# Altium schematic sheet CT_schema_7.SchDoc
size 423 x 414 mm
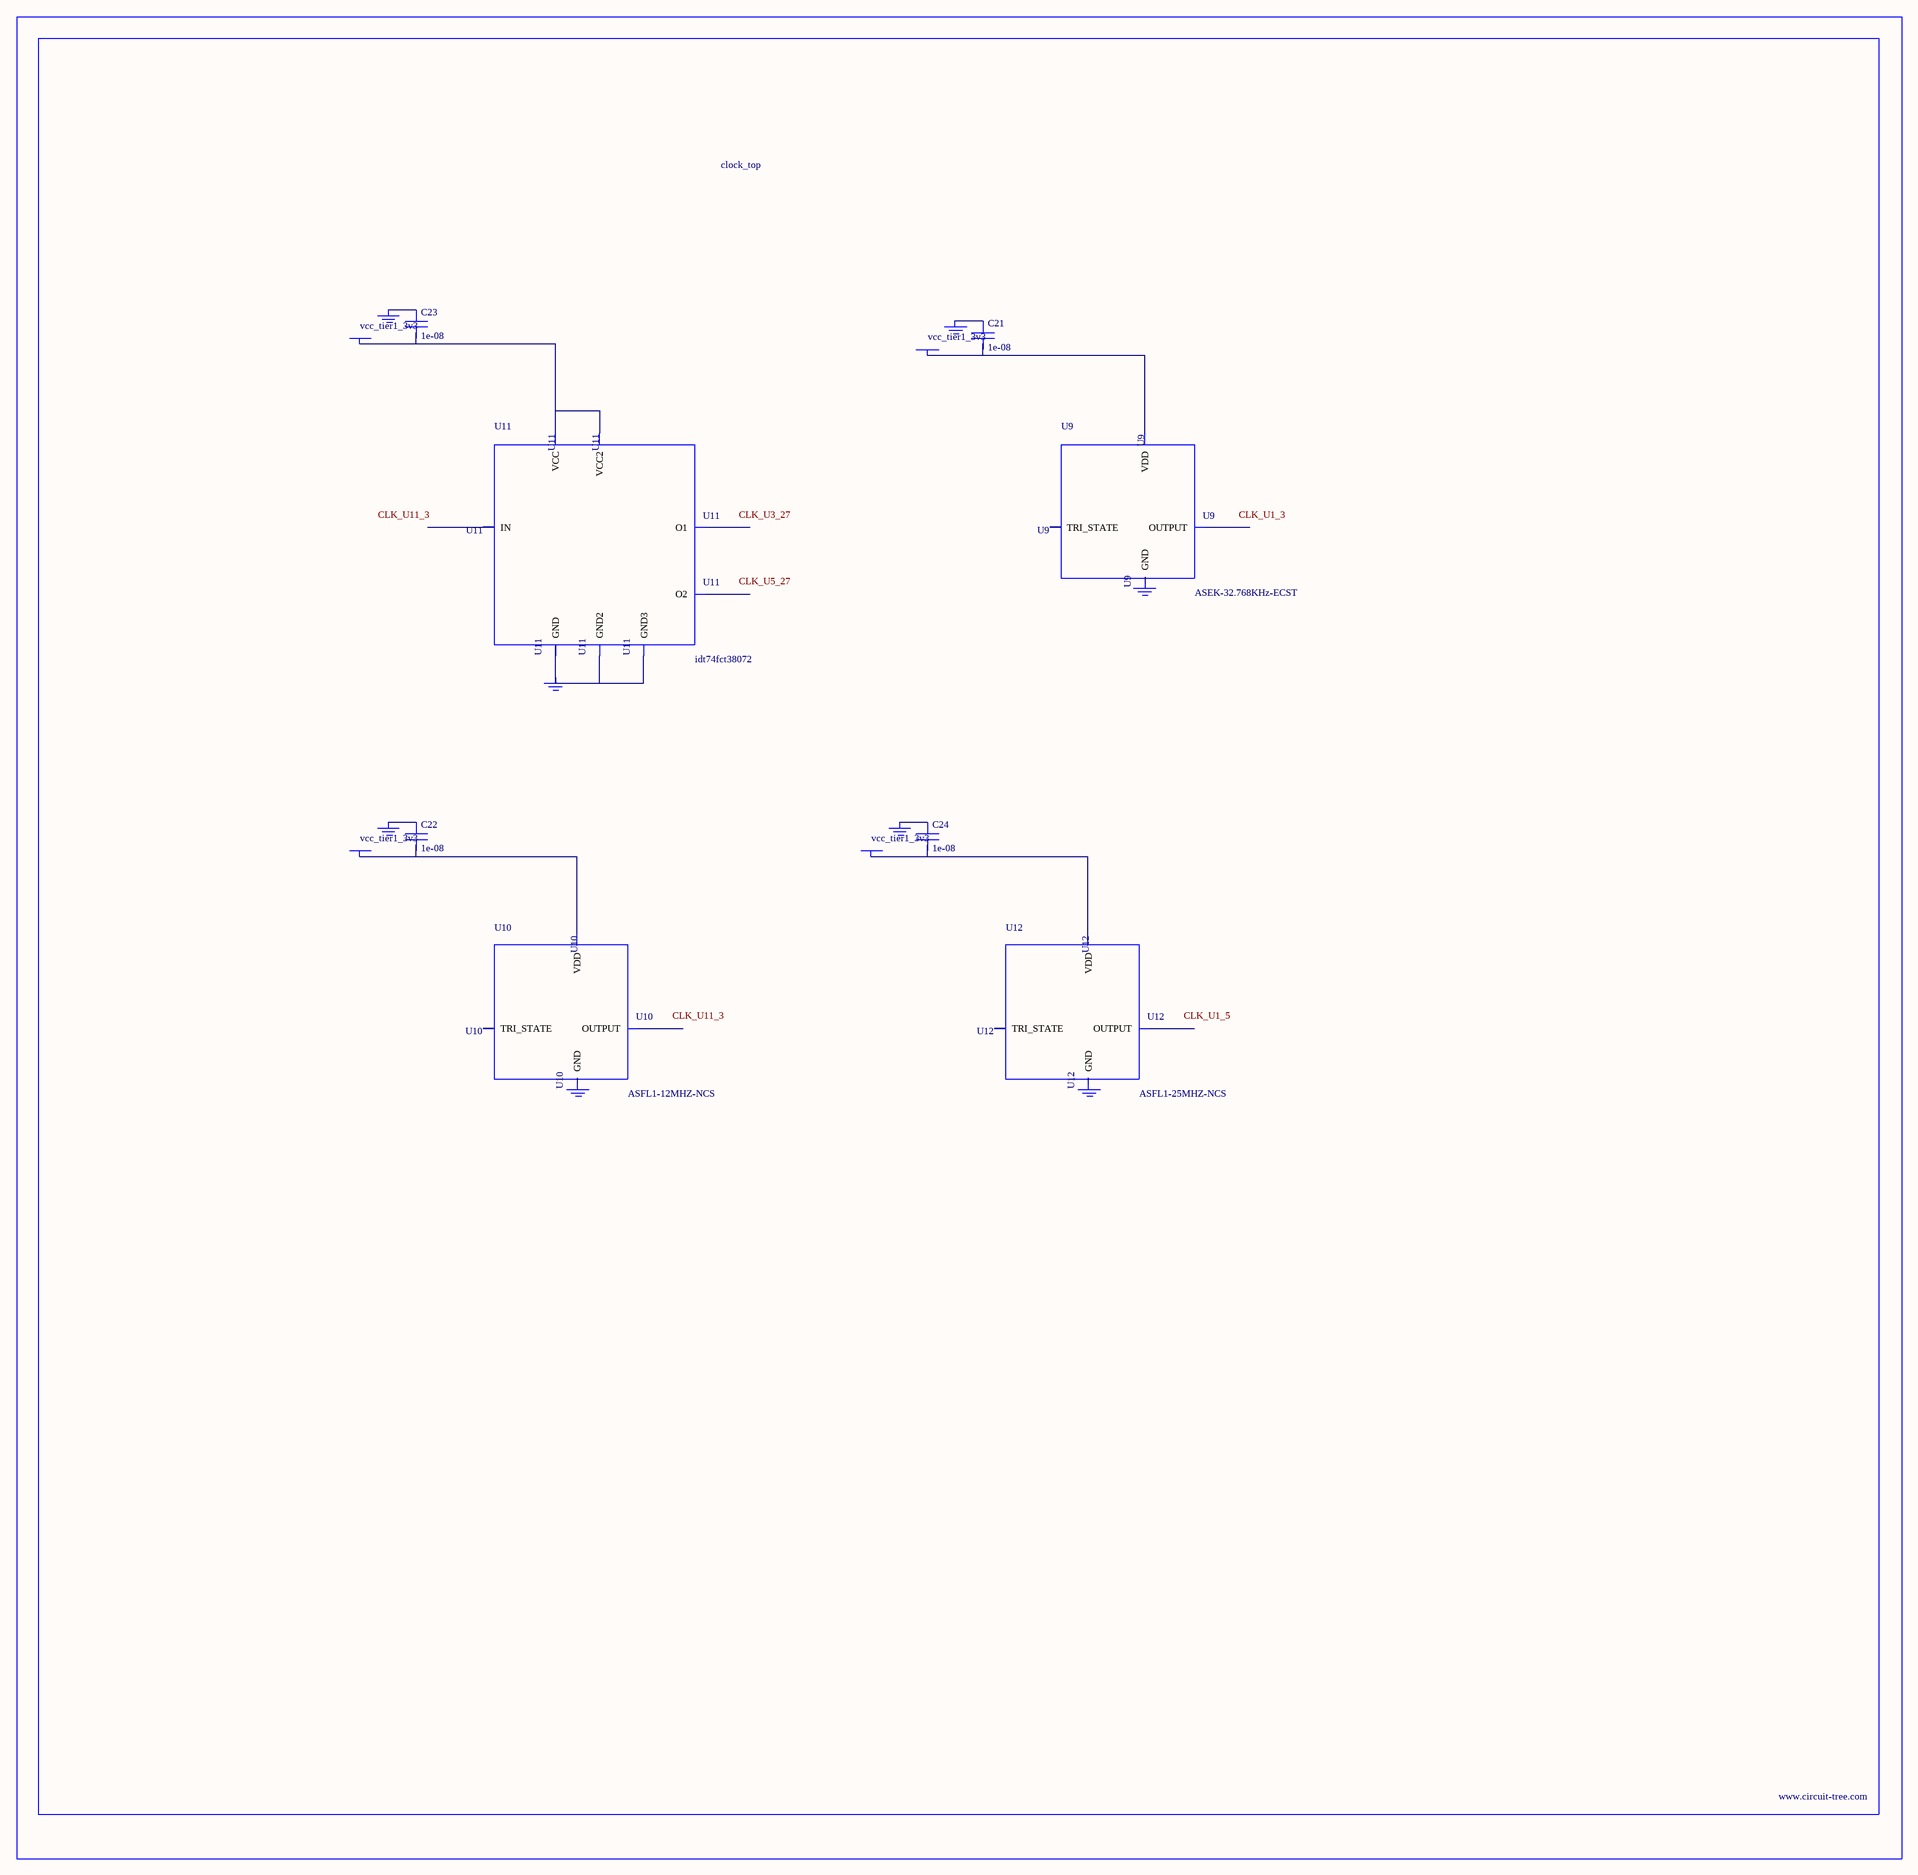
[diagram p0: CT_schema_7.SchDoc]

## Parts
BORDER6  (no value)
C21  1e-08  [C0402]
C22  1e-08  [C0402]
C23  1e-08  [C0402]
C24  1e-08  [C0402]
GND_INSTANCE_6_0  (no value)
GND_INSTANCE_6_1  (no value)
GND_INSTANCE_6_2  (no value)
GND_INSTANCE_6_3  (no value)
GND_INSTANCE_6_4  (no value)
GND_INSTANCE_6_5  (no value)
GND_INSTANCE_6_6  (no value)
GND_INSTANCE_6_7  (no value)
POWER_INSTANCE_6_0  vcc_tier1_3v3
POWER_INSTANCE_6_1  vcc_tier1_3v3
POWER_INSTANCE_6_2  vcc_tier1_3v3
POWER_INSTANCE_6_3  vcc_tier1_3v3
U9  ASEK-32.768KHz-ECST  [ASEK]
U10  ASFL1-12MHZ-NCS  [ASFL1]
U11  idt74fct38072  [IDT74FCT38072]
U12  ASFL1-25MHZ-NCS  [ASFL1]

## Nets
NetC21_1: C21.1 GND_INSTANCE_6_0.0(GND)
NetC21_2: C21.2 POWER_INSTANCE_6_0.0(PWR) U9.4(VDD)
NetC22_1: C22.1 GND_INSTANCE_6_2.0(GND)
NetC22_2: C22.2 POWER_INSTANCE_6_1.0(PWR) U10.4(VDD)
NetC23_1: C23.1 GND_INSTANCE_6_4.0(GND)
NetC23_2: C23.2 POWER_INSTANCE_6_2.0(PWR) U11.1(VCC) U11.2(VCC2)
NetC24_1: C24.1 GND_INSTANCE_6_6.0(GND)
NetC24_2: C24.2 POWER_INSTANCE_6_3.0(PWR) U12.4(VDD)
NetGND_INSTANCE_6_5_0: GND_INSTANCE_6_5.0(GND) U11.4(GND) U11.5(GND2) U11.8(GND3)

Not connected (* = marked no-connect by the designer): GND_INSTANCE_6_1 0(GND); GND_INSTANCE_6_3 0(GND); GND_INSTANCE_6_7 0(GND); U9 1(TRI_STATE) 2(GND) 3(OUTPUT); U10 1(TRI_STATE) 2(GND) 3(OUTPUT); U11 3(IN) 6(O2) 7(O1); U12 1(TRI_STATE) 2(GND) 3(OUTPUT)

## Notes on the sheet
- Labels drawn without touching a wire or pin: CLK_U1_3, CLK_U1_5, CLK_U3_27, CLK_U5_27, CLK_U11_3

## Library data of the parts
BORDER6 = BORDER_PAGE6
C21-C24 = C0402C103K3RAC
GND_INSTANCE_6_0-GND_INSTANCE_6_7 = GND
POWER_INSTANCE_6_0-POWER_INSTANCE_6_3 = PWR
